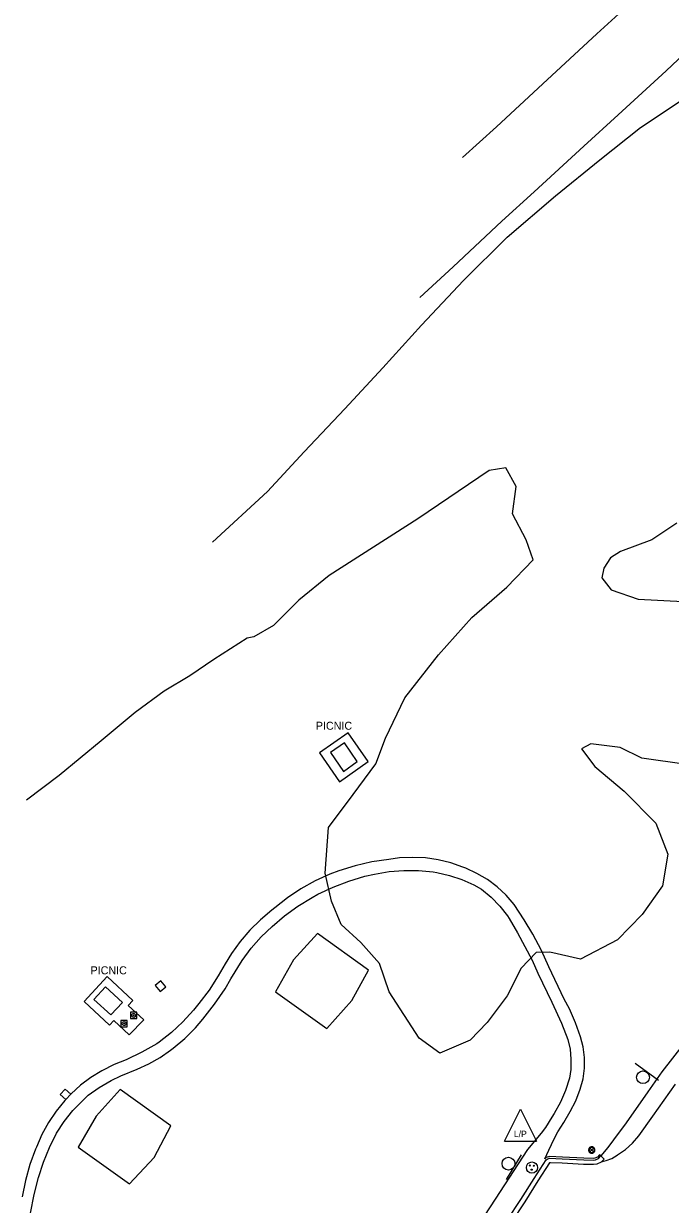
# Model space of a CAD drawing. Extents: x 2161152 to 2175754, y 602179 to 617749.
# Drawn here: x 2162182.3 to 2162384.4, y 604578.1 to 604947 of the extents above; entities that cross this region are included whole.
import ezdxf

# ---------------------------------------------------------------- set-up
doc = ezdxf.new("R2010")
doc.units = 0
for name, color, linetype in [('RD_EX_Bldg', 7, 'Continuous'), ('RD_EX_BldgApp_Post', 7, 'Continuous'), ('RD_EX_BldgApp_Sign', 7, 'Continuous'), ('RD_EX_Conc_Curb', 7, 'Continuous'), ('RD_EX_Conc_Gutter', 7, 'Continuous'), ('RD_EX_Conc_Sidewalk', 7, 'Continuous'), ('RD_EX_Conc_Slab', 7, 'Continuous'), ('RD_EX_DR_Inlet', 7, 'Continuous'), ('RD_EX_Misc', 7, 'Continuous'), ('RD_EX_Misc_Golf_Cartpath', 7, 'Continuous'), ('RD_EX_Parking_Asphalt', 7, 'Continuous'), ('RD_EX_Parking_Conc', 7, 'Continuous'), ('RD_EX_Road', 7, 'Continuous'), ('RD_EX_UT', 7, 'Continuous'), ('RD_EX_VEG', 7, 'Continuous')]:
    doc.layers.add(name, color=color, linetype=linetype)

msp = doc.modelspace()

# ---------------------------------------------------------------- linework, layer by layer
at = {"layer": 'RD_EX_Bldg'}
for points in [[(2162261.06, 604644.53), (2162277.13, 604633.08), (2162284.87, 604641.8), (2162290.08, 604651.21), (2162274.16, 604662.7), (2162266.69, 604654.44), (2162261.06, 604644.53)], [(2162212.5, 604614.01), (2162205.01, 604605.64), (2162199.33, 604595.98), (2162215.37, 604584.48), (2162223.15, 604592.68), (2162228.32, 604602.67), (2162212.5, 604614.01)]]:
    msp.add_lwpolyline(points, dxfattribs=at)
at = {"layer": 'RD_EX_BldgApp_Post'}
for p, q in [((2162360.44, 604594.49), (2162359.3, 604595.63)), ((2162359.3, 604594.49), (2162360.44, 604595.63))]:
    msp.add_line(p, q, dxfattribs=at)
for points in [[(2162360.87, 604595.06), (2162360.86, 604595.22), (2162360.82, 604595.38), (2162360.75, 604595.54), (2162360.64, 604595.7), (2162360.51, 604595.84), (2162360.34, 604595.95), (2162360.16, 604596.02), (2162359.97, 604596.06), (2162359.79, 604596.06), (2162359.61, 604596.03), (2162359.46, 604595.98), (2162359.33, 604595.9), (2162359.2, 604595.81), (2162359.08, 604595.68), (2162358.98, 604595.53), (2162358.91, 604595.35), (2162358.87, 604595.16), (2162358.87, 604594.96), (2162358.91, 604594.77), (2162358.98, 604594.59), (2162359.08, 604594.44), (2162359.2, 604594.32), (2162359.33, 604594.22), (2162359.46, 604594.15), (2162359.61, 604594.09), (2162359.79, 604594.06), (2162359.97, 604594.06), (2162360.16, 604594.1), (2162360.34, 604594.18), (2162360.51, 604594.29), (2162360.64, 604594.42), (2162360.75, 604594.58), (2162360.82, 604594.74), (2162360.86, 604594.91), (2162360.87, 604595.06)], [(2162360.67, 604595.06), (2162360.66, 604595.18), (2162360.63, 604595.31), (2162360.57, 604595.45), (2162360.49, 604595.57), (2162360.38, 604595.68), (2162360.25, 604595.77), (2162360.1, 604595.83), (2162359.95, 604595.86), (2162359.8, 604595.86), (2162359.67, 604595.84), (2162359.54, 604595.79), (2162359.44, 604595.73), (2162359.33, 604595.66), (2162359.24, 604595.56), (2162359.16, 604595.44), (2162359.1, 604595.29), (2162359.07, 604595.14), (2162359.07, 604594.98), (2162359.1, 604594.83), (2162359.16, 604594.69), (2162359.24, 604594.57), (2162359.33, 604594.47), (2162359.44, 604594.39), (2162359.54, 604594.33), (2162359.67, 604594.29), (2162359.8, 604594.26), (2162359.95, 604594.26), (2162360.1, 604594.29), (2162360.25, 604594.35), (2162360.38, 604594.44), (2162360.49, 604594.55), (2162360.57, 604594.68), (2162360.63, 604594.81), (2162360.66, 604594.94), (2162360.67, 604595.06)]]:
    msp.add_lwpolyline(points, dxfattribs=at)
at = {"layer": 'RD_EX_BldgApp_Sign'}
for p, q in [((2162380.7, 604616.8), (2162373.4, 604622.07)), ((2162333.2, 604585.89), (2162337.9, 604593.56))]:
    msp.add_line(p, q, dxfattribs=at)
for centre in [(2162375.85, 604617.8), (2162333.83, 604590.8)]:
    msp.add_circle(centre, 2, dxfattribs=at)
at = {"layer": 'RD_EX_Conc_Curb'}
msp.add_lwpolyline([(2162333.45, 604573.16), (2162337.7, 604579.63), (2162341.82, 604586.18), (2162345.61, 604592), (2162345.91, 604592.25), (2162346.7, 604592.55), (2162350.66, 604592.33), (2162357.34, 604591.98), (2162360.32, 604591.93), (2162361, 604592.02), (2162361.95, 604592.46), (2162362.67, 604593.22), (2162362.57, 604593.32), (2162362.31, 604593.56), (2162361.65, 604592.87), (2162360.86, 604592.5), (2162360.3, 604592.43), (2162357.36, 604592.48), (2162350.69, 604592.83), (2162346.62, 604593.05), (2162345.65, 604592.69), (2162345.23, 604592.33)], dxfattribs=at)
at = {"layer": 'RD_EX_Conc_Gutter'}
msp.add_lwpolyline([(2162362.67, 604593.22), (2162363.7, 604592.23), (2162362.91, 604591.41), (2162362.79, 604591.28), (2162361.4, 604590.63), (2162360.4, 604590.51), (2162357.29, 604590.56), (2162350.59, 604590.91), (2162346.92, 604591.11), (2162346.65, 604591.01), (2162343.02, 604585.41), (2162338.9, 604578.86), (2162334.64, 604572.38)], dxfattribs=at)
at = {"layer": 'RD_EX_Conc_Sidewalk'}
for points in [[(2162345.23, 604592.33), (2162346.45, 604594.99), (2162348.16, 604598.55), (2162349.3, 604600.79), (2162351.15, 604603.71), (2162353.11, 604607.05), (2162354.87, 604610.48), (2162356.28, 604614.07), (2162357.21, 604617.33), (2162357.58, 604620.64), (2162357.56, 604623.97), (2162357.15, 604627.27), (2162356.38, 604630.41), (2162354.8, 604634.85), (2162352.88, 604639.17), (2162351.27, 604642.23), (2162346.44, 604652.31), (2162344.14, 604657.44), (2162341.42, 604662.46), (2162338.78, 604666.98), (2162335.66, 604671.82), (2162333.11, 604674.68), (2162330.3, 604677.26), (2162327.24, 604679.54), (2162323.97, 604681.49), (2162320.53, 604683.09), (2162319.58, 604683.46), (2162315.78, 604684.78), (2162311.86, 604685.74), (2162307.86, 604686.31), (2162303.82, 604686.51), (2162299.77, 604686.32), (2162296.46, 604685.88), (2162291.17, 604685.07), (2162285.94, 604683.88), (2162280.82, 604682.33), (2162278, 604681.3), (2162273.41, 604679.17), (2162268.98, 604676.69), (2162264.77, 604673.88), (2162260.79, 604670.74), (2162259.91, 604669.98), (2162256.33, 604667.01), (2162253.01, 604663.74), (2162249.98, 604660.21), (2162247.26, 604656.43), (2162245.34, 604653.28), (2162243.14, 604649.47), (2162240.3, 604645.02), (2162237.13, 604640.8), (2162235.41, 604638.75), (2162232.09, 604635.16), (2162228.5, 604631.83), (2162224.65, 604628.81), (2162223.92, 604628.29), (2162219.23, 604625.6), (2162214.36, 604623.26), (2162210.62, 604621.75), (2162206.81, 604619.84), (2162203.36, 604617.74), (2162200.13, 604615.31), (2162197.15, 604612.58), (2162197.05, 604612.47), (2162195.51, 604610.81), (2162195.26, 604610.53), (2162192.53, 604607.21), (2162190.12, 604603.66), (2162188.04, 604599.9), (2162186.32, 604595.97), (2162186.09, 604595.37), (2162184.3, 604590.49), (2162182.89, 604585.49), (2162181.85, 604580.4)], [(2162184.53, 604575.37), (2162185.61, 604581.19), (2162187, 604586.44), (2162188.51, 604591.22), (2162190.39, 604595.88), (2162192.59, 604600.3), (2162195.01, 604603.97), (2162197.75, 604607.4), (2162200.79, 604610.58), (2162202.53, 604612.16), (2162205.98, 604614.64), (2162209.64, 604616.78), (2162212.72, 604618.25), (2162217.83, 604620.34), (2162221.5, 604621.98), (2162224.99, 604623.98), (2162228.27, 604626.3), (2162229.05, 604626.93), (2162232.66, 604629.95), (2162236, 604633.27), (2162238.35, 604635.97), (2162241.97, 604640.6), (2162245.28, 604645.47), (2162247.13, 604648.53), (2162250.58, 604654.26), (2162253.44, 604658.09), (2162256.61, 604661.68), (2162259.96, 604664.91), (2162263.89, 604668.26), (2162268.06, 604671.3), (2162272.45, 604674.01), (2162274.29, 604675.01), (2162279.03, 604677.24), (2162283.92, 604679.1), (2162288.94, 604680.6), (2162291.96, 604681.3), (2162296.52, 604682.05), (2162301.12, 604682.41), (2162305.73, 604682.39), (2162310.33, 604681.98), (2162311.44, 604681.82), (2162315.42, 604680.88), (2162319.27, 604679.57), (2162322.98, 604677.89), (2162325.41, 604676.55), (2162328.38, 604674.07), (2162331.09, 604671.29), (2162333.51, 604668.25), (2162334.09, 604667.42), (2162336.62, 604662.93), (2162341.23, 604654.34), (2162342.99, 604650.37), (2162347.43, 604641.29), (2162350.4, 604634.75), (2162352.38, 604629.62), (2162353.07, 604626.54), (2162353.37, 604623.4), (2162353.27, 604620.24), (2162352.88, 604617.53), (2162351.66, 604613.69), (2162350.06, 604609.99), (2162348.12, 604606.46), (2162347.42, 604605.36), (2162345.37, 604602.15), (2162344.01, 604600.37), (2162339.77, 604595.25), (2162329.63, 604579.68), (2162317.88, 604561.71)]]:
    msp.add_lwpolyline(points, dxfattribs=at)
at = {"layer": 'RD_EX_Conc_Slab'}
for points in [[(2162274.83, 604719.19), (2162281.04, 604710.11), (2162290.04, 604716.46), (2162283.76, 604725.43), (2162274.83, 604719.19)], [(2162215.29, 604631.01), (2162210.55, 604635.55), (2162209.16, 604634.07), (2162201.25, 604641.51), (2162208.43, 604649.23), (2162216.45, 604641.83), (2162214.99, 604640.22), (2162219.87, 604635.74), (2162215.29, 604631.01)], [(2162223.4, 604646.46), (2162225.02, 604644.64), (2162226.76, 604646.08), (2162225.18, 604647.96), (2162223.4, 604646.46)], [(2162195.51, 604610.81), (2162193.74, 604612.36), (2162195.31, 604614.08), (2162197.05, 604612.47)]]:
    msp.add_lwpolyline(points, dxfattribs=at)
at = {"layer": 'RD_EX_DR_Inlet'}
for centre, radius in [((2162341.17, 604589.58), 1.75), ((2162340.51, 604590.21), 0.175), ((2162341.73, 604590.14), 0.175), ((2162341.08, 604588.92), 0.175)]:
    msp.add_circle(centre, radius, dxfattribs=at)
at = {"layer": 'RD_EX_Misc'}
for points in [[(2162278.26, 604719.23), (2162282.25, 604713.36), (2162286.59, 604716.42), (2162282.59, 604722.3), (2162278.26, 604719.23)], [(2162204.3, 604642.11), (2162209.6, 604637.3), (2162213.21, 604641.17), (2162207.95, 604646.07), (2162204.3, 604642.11)], [(2162215.71, 604636.12), (2162217.71, 604636.12), (2162217.71, 604638.12), (2162215.71, 604638.12), (2162215.71, 604636.12)], [(2162216.11, 604637.12), (2162216.13, 604637.27), (2162216.19, 604637.42), (2162216.28, 604637.54), (2162216.4, 604637.63), (2162216.54, 604637.7), (2162216.7, 604637.72), (2162216.85, 604637.71), (2162216.99, 604637.65), (2162217.12, 604637.57), (2162217.22, 604637.45), (2162217.28, 604637.31), (2162217.31, 604637.16), (2162217.31, 604637.12)], [(2162212.74, 604633.58), (2162214.74, 604633.58), (2162214.74, 604635.58), (2162212.74, 604635.58), (2162212.74, 604633.58)], [(2162213.14, 604634.58), (2162213.16, 604634.73), (2162213.22, 604634.87), (2162213.31, 604635), (2162213.43, 604635.09), (2162213.57, 604635.15), (2162213.72, 604635.18), (2162213.87, 604635.16), (2162214.02, 604635.11), (2162214.14, 604635.02), (2162214.24, 604634.91), (2162214.31, 604634.77), (2162214.34, 604634.62), (2162214.34, 604634.58)], [(2162214.34, 604634.58), (2162214.32, 604634.43), (2162214.26, 604634.28), (2162214.17, 604634.16), (2162214.05, 604634.07), (2162213.91, 604634), (2162213.76, 604633.98), (2162213.61, 604633.99), (2162213.46, 604634.05), (2162213.34, 604634.13), (2162213.24, 604634.25), (2162213.17, 604634.39), (2162213.14, 604634.54), (2162213.14, 604634.58)], [(2162213.64, 604634.58), (2162213.66, 604634.64), (2162213.71, 604634.67), (2162213.77, 604634.67), (2162213.82, 604634.64), (2162213.84, 604634.58)], [(2162213.84, 604634.58), (2162213.82, 604634.52), (2162213.77, 604634.48), (2162213.71, 604634.48), (2162213.66, 604634.52), (2162213.64, 604634.58)], [(2162217.31, 604637.12), (2162217.29, 604636.97), (2162217.24, 604636.83), (2162217.15, 604636.7), (2162217.03, 604636.61), (2162216.89, 604636.55), (2162216.73, 604636.52), (2162216.58, 604636.54), (2162216.44, 604636.59), (2162216.31, 604636.68), (2162216.21, 604636.79), (2162216.14, 604636.93), (2162216.12, 604637.08), (2162216.11, 604637.12)], [(2162216.61, 604637.12), (2162216.63, 604637.18), (2162216.68, 604637.22), (2162216.75, 604637.22), (2162216.8, 604637.18), (2162216.81, 604637.12)], [(2162216.81, 604637.12), (2162216.8, 604637.06), (2162216.75, 604637.03), (2162216.68, 604637.03), (2162216.63, 604637.06), (2162216.61, 604637.12)]]:
    msp.add_lwpolyline(points, dxfattribs=at)
at = {"layer": 'RD_EX_Parking_Asphalt'}
msp.add_lwpolyline([(2162388.4, 604628), (2162381.73, 604619.45), (2162377.41, 604613.29), (2162370.59, 604603.53), (2162366.7, 604598.27), (2162364.84, 604595.89), (2162362.67, 604593.22)], dxfattribs=at)
at = {"layer": 'RD_EX_Parking_Conc'}
msp.add_lwpolyline([(2162362.91, 604591.41), (2162363.49, 604591.59), (2162364.41, 604591.79), (2162366.17, 604592.46), (2162367.75, 604593.48), (2162367.94, 604593.58), (2162370.41, 604595.25), (2162372.64, 604597.22), (2162374.6, 604599.48), (2162378.93, 604605.66), (2162386.07, 604615.69)], dxfattribs=at)
at = {"layer": 'RD_EX_Road'}
for points in [[(2162372.95, 604954.24), (2162361.49, 604943.79), (2162344.54, 604928.17), (2162330.11, 604914.74), (2162319.46, 604905.15)], [(2162306.15, 604861.41), (2162316.51, 604871.05), (2162331.74, 604885.28), (2162341.86, 604894.51), (2162357.42, 604908.7), (2162368.11, 604918.55), (2162383.08, 604932.31), (2162399.92, 604948.11)]]:
    msp.add_lwpolyline(points, dxfattribs=at)
at = {"layer": 'RD_EX_UT'}
for p, q in [((2162332.55, 604597.81), (2162337.55, 604607.81)), ((2162337.55, 604607.81), (2162342.55, 604597.81)), ((2162332.55, 604597.81), (2162342.55, 604597.81))]:
    msp.add_line(p, q, dxfattribs=at)
at = {"layer": 'RD_EX_VEG'}
for points in [[(2162241.4, 604784.98), (2162258.49, 604800.83), (2162270.04, 604813.23), (2162282.69, 604826.68), (2162294.59, 604839.49), (2162306.66, 604852.76), (2162319.74, 604866.71), (2162333.43, 604880.34), (2162348.49, 604893.25), (2162362.33, 604904.46), (2162375.04, 604914.58), (2162389, 604923.8), (2162399.81, 604931.04), (2162410.65, 604937.78), (2162419.24, 604943.19), (2162426.23, 604945.17), (2162431.96, 604947.21)], [(2162389.51, 604715.49), (2162375.51, 604717.48), (2162368.69, 604720.88), (2162359.6, 604722.01), (2162356.61, 604720.42), (2162360.85, 604714.92), (2162370.01, 604707.21), (2162379.85, 604697.22), (2162383.58, 604687.47), (2162382.01, 604677.58), (2162375.65, 604668.67), (2162367.89, 604660.75), (2162356.36, 604654.7), (2162346.76, 604656.85), (2162342.49, 604656.81), (2162337.83, 604651.87), (2162333.4, 604643.23), (2162327.17, 604634.9), (2162321.87, 604629.35), (2162312.35, 604625.31), (2162305.93, 604629.99), (2162296.55, 604644.47), (2162293.53, 604653.38), (2162287.75, 604659.93), (2162281.57, 604665.49), (2162278.53, 604672.8), (2162276.59, 604681.61), (2162277.56, 604695.86), (2162285.31, 604706.1), (2162292.36, 604715.75), (2162295.46, 604723.7), (2162301.46, 604736.4), (2162311.92, 604749.78), (2162322.39, 604761.43), (2162333.31, 604770.97), (2162341.58, 604779.52), (2162339.32, 604785.71), (2162335.06, 604793.81), (2162336.26, 604802.42), (2162332.99, 604808.24), (2162327.76, 604807.42), (2162305.55, 604792.3), (2162277.85, 604774.53), (2162268.31, 604766.85), (2162260.37, 604758.91), (2162254.32, 604755.42), (2162252.21, 604754.96), (2162241.72, 604748.33), (2162234.23, 604743.22), (2162226.23, 604738.39), (2162217.21, 604731.81), (2162206.54, 604722.9), (2162193.42, 604712.07), (2162183.27, 604704.41)], [(2162386.39, 604790.92), (2162378.58, 604785.75), (2162368.87, 604782.08), (2162365.67, 604780.06), (2162363.65, 604776.91), (2162362.98, 604773.85), (2162365.9, 604770.1), (2162374.34, 604767.14), (2162388.4, 604766.41)]]:
    msp.add_lwpolyline(points, dxfattribs=at)

# ---------------------------------------------------------------- texts
at = {"layer": 'RD_EX_Misc_Golf_Cartpath'}
for p in [(2162273.65, 604726.38), (2162203.26, 604649.96)]:
    msp.add_text('PICNIC', height=2.5, dxfattribs=at).set_placement(p)
at = {"layer": 'RD_EX_UT'}
msp.add_text('L/P', height=2, dxfattribs=at).set_placement((2162335.54, 604599.09))

doc.saveas('drawing.dxf')
